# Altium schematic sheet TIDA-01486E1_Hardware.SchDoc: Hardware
size 431 x 279 mm; Date: Not shown in title block; ApprovedBy: Not shown in title block; CheckedBy: Not shown in title block; Author: Not shown in title block; CompanyName: Not shown in title block; DrawnBy: Giovanni Campanella; Engineer: Giovanni Campanella; Organization: Not shown in title block; Address1: Not shown in title block; Address2: Not shown in title block; Address3: Not shown in title block; Address4: Not shown in title block; DocumentNumber: 1; Revision: Use project parameter SCH_Rev; SheetNumber: 3; SheetTotal: 3; PageSetup: Record=PageOptions¦CenterHorizontal=True¦CenterVertical=True¦PrintScale=1.00¦XCorrection=1.00¦YCorrection=1.00¦PrintKind=0¦BorderSize=5000000¦LeftOffset=0¦BottomOffset=0¦Orientation=2¦PaperLength=1000¦PaperWidth=1000¦Scale=100¦PaperSource=15¦PrintQuality=600¦MediaType=1¦DitherType=10¦PaperKind=Letter¦PrintScaleMode=1
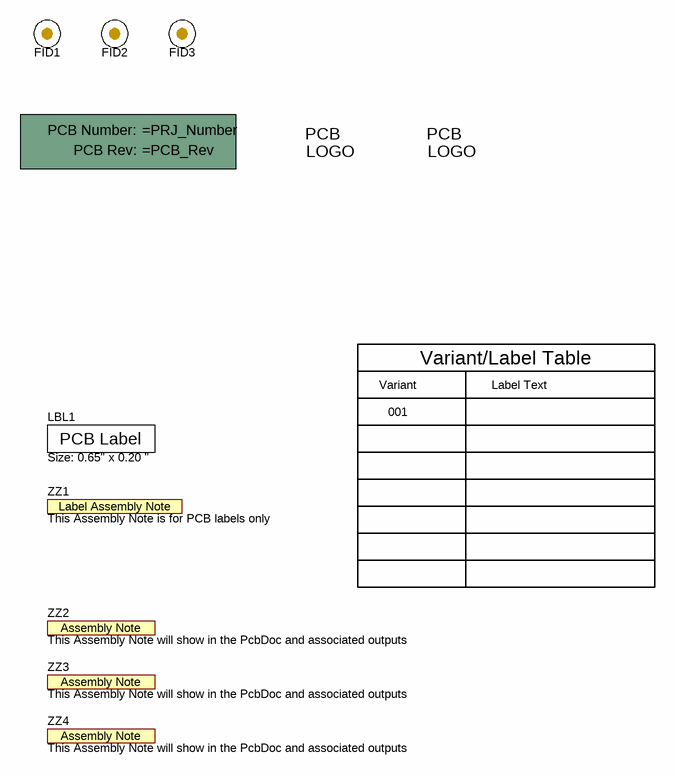
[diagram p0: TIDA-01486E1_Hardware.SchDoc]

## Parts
!PCB  Printed Circuit Board  (value not drawn)  (mechanical)
FID1  Fiducial  [Fiducial10-20]  (value not drawn)
FID2  Fiducial  [Fiducial10-20]  (value not drawn)
FID3  Fiducial  [Fiducial10-20]  (value not drawn)
LBL1  Size: 0.65" x 0.20 "  [Label_650x200]
Logo2  Pb-Free Symbol  [Pb-Free_Overlay_Small]  (value not drawn)  (no BOM)
Logo3  FCC disclaimer  [FCC_disclaimer]  (value not drawn)  (no BOM)
ZZ1  This Assembly Note is for PCB labels only  [AssemblyNoteLabel]  (no BOM)
ZZ2  This Assembly Note will show in the PcbDoc and associated outputs  [AssemblyNote]  (no BOM)
ZZ3  This Assembly Note will show in the PcbDoc and associated outputs  [AssemblyNote]  (no BOM)
ZZ4  This Assembly Note will show in the PcbDoc and associated outputs  [AssemblyNote]  (no BOM)

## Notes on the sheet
- Variant/Label Table
- Variant
- 001
- Label Text

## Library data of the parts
!PCB = PCB: Manufacturer: Any; SymbolCreator: a0412235
FID1-FID3 = Fiducial: Fiducial mark.  There is nothing to buy or mount.; SymbolCreator: codlsc
LBL1 = THT-14-423-10: Thermal Transfer Printable Labels, 0.650" W x 0.200" H - 10,000 per roll; Manufacturer: Brady; SymbolCreator: a0412235; CompType: Label; Green_Lifecycle: Not Set; Green_REACh: Incomplete
Logo2 = Pb-Free: SymbolCreator: a0412235
Logo3 = FCC_disclaimer: SymbolCreator: a0412235
ZZ1 = AssemblyNoteLabel: SymbolCreator: a0412235
ZZ2-ZZ4 = AssemblyNote: SymbolCreator: codlsc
